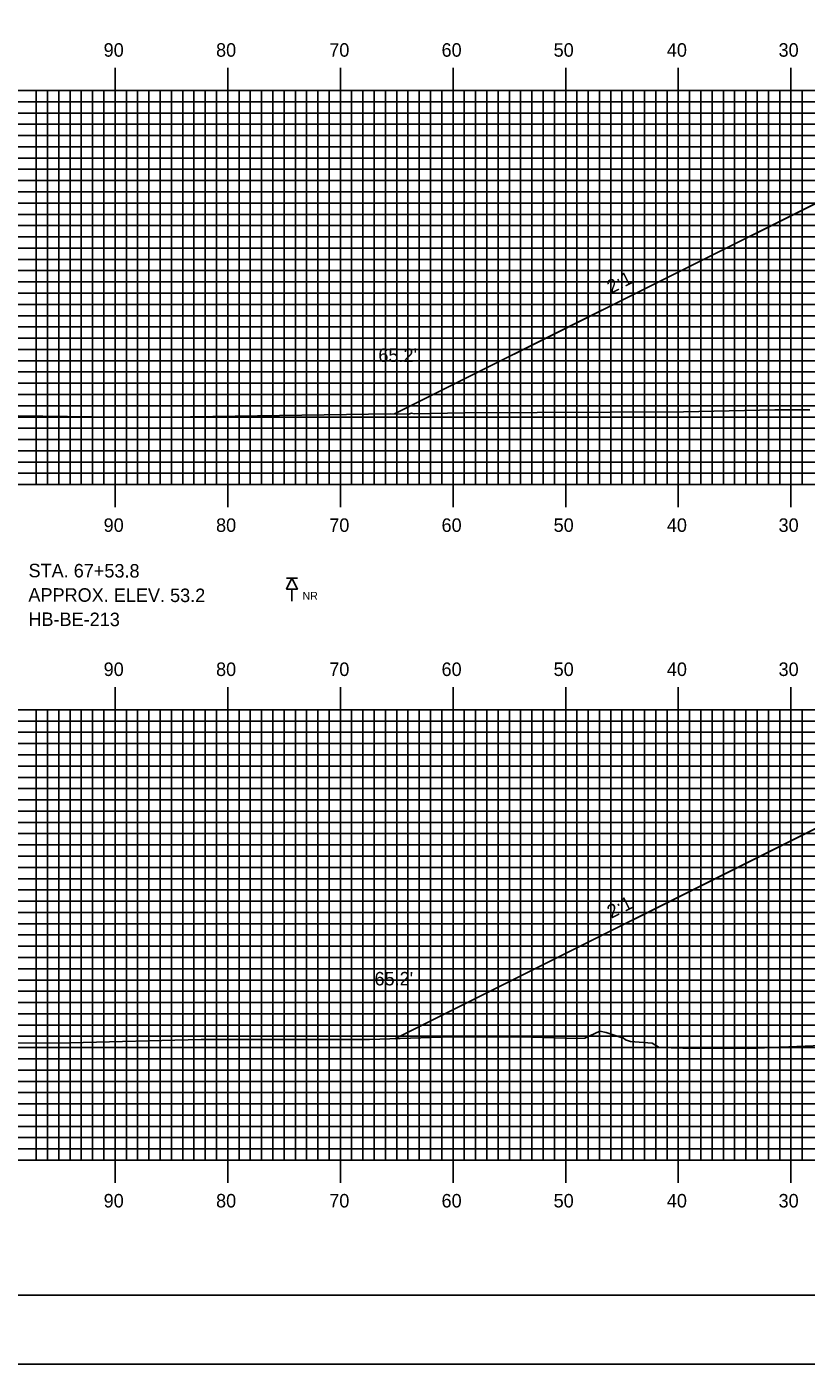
# Model space of a CAD drawing. Extents: x 1759430 to 1759773, y 442591 to 442811.
# Drawn here: x 1759497.8 to 1759567, y 442590.5 to 442709.3 of the extents above; entities that cross this region are included whole.
import ezdxf

# ---------------------------------------------------------------- set-up
doc = ezdxf.new("R2010")
doc.units = 0
for name, color, linetype in [('ANNOTATION', 7, 'Continuous'), ('BORDER', 7, 'Continuous'), ('BORING - NO REFUSAL', 7, 'Continuous'), ('D_Roadway_Centerline', 7, 'Continuous'), ('D_Roadway_SlopeLines', 7, 'Continuous'), ('D_Text_Standard', 7, 'Continuous'), ('H_V ANNOTATION', 7, 'Continuous'), ('MAJOR', 7, 'Continuous'), ('MINOR', 7, 'Continuous'), ('PLOT BOUNDARY', 7, 'Continuous'), ('S_Roadway_Centerline', 7, 'Continuous')]:
    doc.layers.add(name, color=color, linetype=linetype)

msp = doc.modelspace()

# ---------------------------------------------------------------- linework, layer by layer
at = {"layer": 'BORDER'}
msp.add_lwpolyline([(1759446.07, 442596.67), (1759766.07, 442596.67), (1759766.07, 442806.67), (1759446.07, 442806.67)], close=True, dxfattribs=at)
at = {"layer": 'BORING - NO REFUSAL'}
for p, q in [((1759521.85, 442660.35), (1759520.89, 442660.35)), ((1759521.37, 442659.39), (1759521.37, 442658.33))]:
    msp.add_line(p, q, dxfattribs=at)
msp.add_lwpolyline([(1759521.37, 442660.35), (1759521.85, 442659.39), (1759520.89, 442659.39)], close=True, dxfattribs=at)
at = {"layer": 'D_Roadway_Centerline'}
for points in [[(1759530.46, 442674.94), (1759567.38, 442693.4), (1759572.67, 442696.04), (1759575.67, 442696.16), (1759583.67, 442696.48), (1759595.67, 442696.91), (1759607.67, 442697.35), (1759619.67, 442697.78), (1759627.67, 442697.46), (1759630.67, 442697.34), (1759635.42, 442694.96), (1759674.27, 442675.54)], [(1759530.5, 442619.46), (1759567.38, 442637.9), (1759572.67, 442640.54), (1759575.67, 442640.66), (1759583.67, 442640.98), (1759595.67, 442641.41), (1759607.67, 442641.85), (1759619.67, 442642.28), (1759627.67, 442641.96), (1759630.67, 442641.84), (1759635.42, 442639.46), (1759673.76, 442620.3)]]:
    msp.add_lwpolyline(points, dxfattribs=at)
at = {"layer": 'D_Roadway_SlopeLines'}
for points in [[(1759572.67, 442696.04), (1759530.46, 442674.94)], [(1759572.67, 442640.54), (1759530.5, 442619.46)]]:
    msp.add_lwpolyline(points, dxfattribs=at)
at = {"layer": 'MAJOR'}
for p, q in [((1759505.67, 442705.67), (1759505.67, 442703.67)), ((1759515.67, 442705.67), (1759515.67, 442703.67)), ((1759525.67, 442705.67), (1759525.67, 442703.67)), ((1759535.67, 442705.67), (1759535.67, 442703.67)), ((1759545.67, 442705.67), (1759545.67, 442703.67)), ((1759555.67, 442705.67), (1759555.67, 442703.67)), ((1759565.67, 442705.67), (1759565.67, 442703.67)), ((1759455.67, 442703.67), (1759735.67, 442703.67)), ((1759455.67, 442703.67), (1759735.67, 442703.67)), ((1759505.67, 442668.67), (1759505.67, 442703.67)), ((1759515.67, 442668.67), (1759515.67, 442703.67)), ((1759525.67, 442668.67), (1759525.67, 442703.67)), ((1759535.67, 442668.67), (1759535.67, 442703.67)), ((1759545.67, 442668.67), (1759545.67, 442703.67)), ((1759555.67, 442668.67), (1759555.67, 442703.67)), ((1759565.67, 442668.67), (1759565.67, 442703.67)), ((1759455.67, 442698.67), (1759735.67, 442698.67)), ((1759455.67, 442693.67), (1759735.67, 442693.67)), ((1759455.67, 442688.67), (1759735.67, 442688.67)), ((1759455.67, 442683.67), (1759735.67, 442683.67)), ((1759455.67, 442678.67), (1759735.67, 442678.67)), ((1759455.67, 442673.67), (1759735.67, 442673.67)), ((1759455.67, 442668.67), (1759735.67, 442668.67)), ((1759455.67, 442668.67), (1759735.67, 442668.67)), ((1759505.67, 442666.66), (1759505.67, 442668.67)), ((1759515.67, 442666.66), (1759515.67, 442668.67)), ((1759525.67, 442666.66), (1759525.67, 442668.67)), ((1759535.67, 442666.66), (1759535.67, 442668.67)), ((1759545.67, 442666.66), (1759545.67, 442668.67)), ((1759555.67, 442666.66), (1759555.67, 442668.67)), ((1759565.67, 442666.66), (1759565.67, 442668.67)), ((1759505.67, 442650.67), (1759505.67, 442648.67)), ((1759515.67, 442650.67), (1759515.67, 442648.67)), ((1759525.67, 442650.67), (1759525.67, 442648.67)), ((1759535.67, 442650.67), (1759535.67, 442648.67)), ((1759545.67, 442650.67), (1759545.67, 442648.67)), ((1759555.67, 442650.67), (1759555.67, 442648.67)), ((1759565.67, 442650.67), (1759565.67, 442648.67)), ((1759455.67, 442648.67), (1759735.67, 442648.67)), ((1759455.67, 442648.67), (1759735.67, 442648.67)), ((1759505.67, 442608.67), (1759505.67, 442648.67)), ((1759515.67, 442608.67), (1759515.67, 442648.67)), ((1759525.67, 442608.67), (1759525.67, 442648.67)), ((1759535.67, 442608.67), (1759535.67, 442648.67)), ((1759545.67, 442608.67), (1759545.67, 442648.67)), ((1759555.67, 442608.67), (1759555.67, 442648.67)), ((1759565.67, 442608.67), (1759565.67, 442648.67)), ((1759455.67, 442643.67), (1759735.67, 442643.67)), ((1759455.67, 442638.67), (1759735.67, 442638.67)), ((1759455.67, 442633.67), (1759735.67, 442633.67)), ((1759455.67, 442628.67), (1759735.67, 442628.67)), ((1759455.67, 442623.67), (1759735.67, 442623.67)), ((1759455.67, 442618.67), (1759735.67, 442618.67)), ((1759455.67, 442613.67), (1759735.67, 442613.67)), ((1759455.67, 442608.67), (1759735.67, 442608.67)), ((1759455.67, 442608.67), (1759735.67, 442608.67)), ((1759505.67, 442606.66), (1759505.67, 442608.67)), ((1759515.67, 442606.66), (1759515.67, 442608.67)), ((1759525.67, 442606.66), (1759525.67, 442608.67)), ((1759535.67, 442606.66), (1759535.67, 442608.67)), ((1759545.67, 442606.66), (1759545.67, 442608.67)), ((1759555.67, 442606.66), (1759555.67, 442608.67)), ((1759565.67, 442606.66), (1759565.67, 442608.67))]:
    msp.add_line(p, q, dxfattribs=at)
at = {"layer": 'MINOR'}
for p, q in [((1759455.67, 442702.67), (1759735.67, 442702.67)), ((1759498.67, 442668.67), (1759498.67, 442703.67)), ((1759499.67, 442668.67), (1759499.67, 442703.67)), ((1759500.67, 442668.67), (1759500.67, 442703.67)), ((1759501.67, 442668.67), (1759501.67, 442703.67)), ((1759502.67, 442668.67), (1759502.67, 442703.67)), ((1759503.67, 442668.67), (1759503.67, 442703.67)), ((1759504.67, 442668.67), (1759504.67, 442703.67)), ((1759506.67, 442668.67), (1759506.67, 442703.67)), ((1759507.67, 442668.67), (1759507.67, 442703.67)), ((1759508.67, 442668.67), (1759508.67, 442703.67)), ((1759509.67, 442668.67), (1759509.67, 442703.67)), ((1759510.67, 442668.67), (1759510.67, 442703.67)), ((1759511.67, 442668.67), (1759511.67, 442703.67)), ((1759512.67, 442668.67), (1759512.67, 442703.67)), ((1759513.67, 442668.67), (1759513.67, 442703.67)), ((1759514.67, 442668.67), (1759514.67, 442703.67)), ((1759516.67, 442668.67), (1759516.67, 442703.67)), ((1759517.67, 442668.67), (1759517.67, 442703.67)), ((1759518.67, 442668.67), (1759518.67, 442703.67)), ((1759519.67, 442668.67), (1759519.67, 442703.67)), ((1759520.67, 442668.67), (1759520.67, 442703.67)), ((1759521.67, 442668.67), (1759521.67, 442703.67)), ((1759522.67, 442668.67), (1759522.67, 442703.67)), ((1759523.67, 442668.67), (1759523.67, 442703.67)), ((1759524.67, 442668.67), (1759524.67, 442703.67)), ((1759526.67, 442668.67), (1759526.67, 442703.67)), ((1759527.67, 442668.67), (1759527.67, 442703.67)), ((1759528.67, 442668.67), (1759528.67, 442703.67)), ((1759529.67, 442668.67), (1759529.67, 442703.67)), ((1759530.67, 442668.67), (1759530.67, 442703.67)), ((1759531.67, 442668.67), (1759531.67, 442703.67)), ((1759532.67, 442668.67), (1759532.67, 442703.67)), ((1759533.67, 442668.67), (1759533.67, 442703.67)), ((1759534.67, 442668.67), (1759534.67, 442703.67)), ((1759536.67, 442668.67), (1759536.67, 442703.67)), ((1759537.67, 442668.67), (1759537.67, 442703.67)), ((1759538.67, 442668.67), (1759538.67, 442703.67)), ((1759539.67, 442668.67), (1759539.67, 442703.67)), ((1759540.67, 442668.67), (1759540.67, 442703.67)), ((1759541.67, 442668.67), (1759541.67, 442703.67)), ((1759542.67, 442668.67), (1759542.67, 442703.67)), ((1759543.67, 442668.67), (1759543.67, 442703.67)), ((1759544.67, 442668.67), (1759544.67, 442703.67)), ((1759546.67, 442668.67), (1759546.67, 442703.67)), ((1759547.67, 442668.67), (1759547.67, 442703.67)), ((1759548.67, 442668.67), (1759548.67, 442703.67)), ((1759549.67, 442668.67), (1759549.67, 442703.67)), ((1759550.67, 442668.67), (1759550.67, 442703.67)), ((1759551.67, 442668.67), (1759551.67, 442703.67)), ((1759552.67, 442668.67), (1759552.67, 442703.67)), ((1759553.67, 442668.67), (1759553.67, 442703.67)), ((1759554.67, 442668.67), (1759554.67, 442703.67)), ((1759556.67, 442668.67), (1759556.67, 442703.67)), ((1759557.67, 442668.67), (1759557.67, 442703.67)), ((1759558.67, 442668.67), (1759558.67, 442703.67)), ((1759559.67, 442668.67), (1759559.67, 442703.67)), ((1759560.67, 442668.67), (1759560.67, 442703.67)), ((1759561.67, 442668.67), (1759561.67, 442703.67)), ((1759562.67, 442668.67), (1759562.67, 442703.67)), ((1759563.67, 442668.67), (1759563.67, 442703.67)), ((1759564.67, 442668.67), (1759564.67, 442703.67)), ((1759566.67, 442668.67), (1759566.67, 442703.67)), ((1759455.67, 442701.67), (1759735.67, 442701.67)), ((1759455.67, 442700.67), (1759735.67, 442700.67)), ((1759455.67, 442699.67), (1759735.67, 442699.67)), ((1759455.67, 442697.67), (1759735.67, 442697.67)), ((1759455.67, 442696.67), (1759735.67, 442696.67)), ((1759455.67, 442695.67), (1759735.67, 442695.67)), ((1759455.67, 442694.67), (1759735.67, 442694.67)), ((1759455.67, 442692.67), (1759735.67, 442692.67)), ((1759455.67, 442691.67), (1759735.67, 442691.67)), ((1759455.67, 442690.67), (1759735.67, 442690.67)), ((1759455.67, 442689.67), (1759735.67, 442689.67)), ((1759455.67, 442687.67), (1759735.67, 442687.67)), ((1759455.67, 442686.67), (1759735.67, 442686.67)), ((1759455.67, 442685.67), (1759735.67, 442685.67)), ((1759455.67, 442684.67), (1759735.67, 442684.67)), ((1759455.67, 442682.67), (1759735.67, 442682.67)), ((1759455.67, 442681.67), (1759735.67, 442681.67)), ((1759455.67, 442680.67), (1759735.67, 442680.67)), ((1759455.67, 442679.67), (1759735.67, 442679.67)), ((1759455.67, 442677.67), (1759735.67, 442677.67)), ((1759455.67, 442676.67), (1759735.67, 442676.67)), ((1759455.67, 442675.67), (1759735.67, 442675.67)), ((1759455.67, 442674.67), (1759735.67, 442674.67)), ((1759455.67, 442672.67), (1759735.67, 442672.67)), ((1759455.67, 442671.67), (1759735.67, 442671.67)), ((1759455.67, 442670.67), (1759735.67, 442670.67)), ((1759455.67, 442669.67), (1759735.67, 442669.67)), ((1759498.67, 442608.67), (1759498.67, 442648.67)), ((1759499.67, 442608.67), (1759499.67, 442648.67)), ((1759500.67, 442608.67), (1759500.67, 442648.67)), ((1759501.67, 442608.67), (1759501.67, 442648.67)), ((1759502.67, 442608.67), (1759502.67, 442648.67)), ((1759503.67, 442608.67), (1759503.67, 442648.67)), ((1759504.67, 442608.67), (1759504.67, 442648.67)), ((1759506.67, 442608.67), (1759506.67, 442648.67)), ((1759507.67, 442608.67), (1759507.67, 442648.67)), ((1759508.67, 442608.67), (1759508.67, 442648.67)), ((1759509.67, 442608.67), (1759509.67, 442648.67)), ((1759510.67, 442608.67), (1759510.67, 442648.67)), ((1759511.67, 442608.67), (1759511.67, 442648.67)), ((1759512.67, 442608.67), (1759512.67, 442648.67)), ((1759513.67, 442608.67), (1759513.67, 442648.67)), ((1759514.67, 442608.67), (1759514.67, 442648.67)), ((1759516.67, 442608.67), (1759516.67, 442648.67)), ((1759517.67, 442608.67), (1759517.67, 442648.67)), ((1759518.67, 442608.67), (1759518.67, 442648.67)), ((1759519.67, 442608.67), (1759519.67, 442648.67)), ((1759520.67, 442608.67), (1759520.67, 442648.67)), ((1759521.67, 442608.67), (1759521.67, 442648.67)), ((1759522.67, 442608.67), (1759522.67, 442648.67)), ((1759523.67, 442608.67), (1759523.67, 442648.67)), ((1759524.67, 442608.67), (1759524.67, 442648.67)), ((1759526.67, 442608.67), (1759526.67, 442648.67)), ((1759527.67, 442608.67), (1759527.67, 442648.67)), ((1759528.67, 442608.67), (1759528.67, 442648.67)), ((1759529.67, 442608.67), (1759529.67, 442648.67)), ((1759530.67, 442608.67), (1759530.67, 442648.67)), ((1759531.67, 442608.67), (1759531.67, 442648.67)), ((1759532.67, 442608.67), (1759532.67, 442648.67)), ((1759533.67, 442608.67), (1759533.67, 442648.67)), ((1759534.67, 442608.67), (1759534.67, 442648.67)), ((1759536.67, 442608.67), (1759536.67, 442648.67)), ((1759537.67, 442608.67), (1759537.67, 442648.67)), ((1759538.67, 442608.67), (1759538.67, 442648.67)), ((1759539.67, 442608.67), (1759539.67, 442648.67)), ((1759540.67, 442608.67), (1759540.67, 442648.67)), ((1759541.67, 442608.67), (1759541.67, 442648.67)), ((1759542.67, 442608.67), (1759542.67, 442648.67)), ((1759543.67, 442608.67), (1759543.67, 442648.67)), ((1759544.67, 442608.67), (1759544.67, 442648.67)), ((1759546.67, 442608.67), (1759546.67, 442648.67)), ((1759547.67, 442608.67), (1759547.67, 442648.67)), ((1759548.67, 442608.67), (1759548.67, 442648.67)), ((1759549.67, 442608.67), (1759549.67, 442648.67)), ((1759550.67, 442608.67), (1759550.67, 442648.67)), ((1759551.67, 442608.67), (1759551.67, 442648.67)), ((1759552.67, 442608.67), (1759552.67, 442648.67)), ((1759553.67, 442608.67), (1759553.67, 442648.67)), ((1759554.67, 442608.67), (1759554.67, 442648.67)), ((1759556.67, 442608.67), (1759556.67, 442648.67)), ((1759557.67, 442608.67), (1759557.67, 442648.67)), ((1759558.67, 442608.67), (1759558.67, 442648.67)), ((1759559.67, 442608.67), (1759559.67, 442648.67)), ((1759560.67, 442608.67), (1759560.67, 442648.67)), ((1759561.67, 442608.67), (1759561.67, 442648.67)), ((1759562.67, 442608.67), (1759562.67, 442648.67)), ((1759563.67, 442608.67), (1759563.67, 442648.67)), ((1759564.67, 442608.67), (1759564.67, 442648.67)), ((1759566.67, 442608.67), (1759566.67, 442648.67)), ((1759455.67, 442647.67), (1759735.67, 442647.67)), ((1759455.67, 442646.67), (1759735.67, 442646.67)), ((1759455.67, 442645.67), (1759735.67, 442645.67)), ((1759455.67, 442644.67), (1759735.67, 442644.67)), ((1759455.67, 442642.67), (1759735.67, 442642.67)), ((1759455.67, 442641.67), (1759735.67, 442641.67)), ((1759455.67, 442640.67), (1759735.67, 442640.67)), ((1759455.67, 442639.67), (1759735.67, 442639.67)), ((1759455.67, 442637.67), (1759735.67, 442637.67)), ((1759455.67, 442636.67), (1759735.67, 442636.67)), ((1759455.67, 442635.67), (1759735.67, 442635.67)), ((1759455.67, 442634.67), (1759735.67, 442634.67)), ((1759455.67, 442632.67), (1759735.67, 442632.67)), ((1759455.67, 442631.67), (1759735.67, 442631.67)), ((1759455.67, 442630.67), (1759735.67, 442630.67)), ((1759455.67, 442629.67), (1759735.67, 442629.67)), ((1759455.67, 442627.67), (1759735.67, 442627.67)), ((1759455.67, 442626.67), (1759735.67, 442626.67)), ((1759455.67, 442625.67), (1759735.67, 442625.67)), ((1759455.67, 442624.67), (1759735.67, 442624.67)), ((1759455.67, 442622.67), (1759735.67, 442622.67)), ((1759455.67, 442621.67), (1759735.67, 442621.67)), ((1759455.67, 442620.67), (1759735.67, 442620.67)), ((1759455.67, 442619.67), (1759735.67, 442619.67)), ((1759455.67, 442617.67), (1759735.67, 442617.67)), ((1759455.67, 442616.67), (1759735.67, 442616.67)), ((1759455.67, 442615.67), (1759735.67, 442615.67)), ((1759455.67, 442614.67), (1759735.67, 442614.67)), ((1759455.67, 442612.67), (1759735.67, 442612.67)), ((1759455.67, 442611.67), (1759735.67, 442611.67)), ((1759455.67, 442610.67), (1759735.67, 442610.67)), ((1759455.67, 442609.67), (1759735.67, 442609.67))]:
    msp.add_line(p, q, dxfattribs=at)
at = {"layer": 'PLOT BOUNDARY'}
msp.add_lwpolyline([(1759429.89, 442590.55), (1759769.89, 442590.55), (1759769.89, 442810.55), (1759429.89, 442810.55)], close=True, dxfattribs=at)
at = {"layer": 'S_Roadway_Centerline'}
for points in [[(1759455.67, 442674.66), (1759461.59, 442674.85), (1759467.75, 442674.83), (1759480.85, 442674.86), (1759483.88, 442674.88), (1759486.06, 442674.93), (1759505.83, 442674.67), (1759508.01, 442674.65), (1759508.44, 442674.64), (1759530.15, 442674.94), (1759531.73, 442674.91), (1759531.98, 442675.01), (1759532.23, 442674.94), (1759536.65, 442675.05), (1759556.12, 442675.12), (1759564.25, 442675.3), (1759567.34, 442675.32)], [(1759455.67, 442619.06), (1759479.21, 442619.13), (1759483.37, 442619.07), (1759501.67, 442619.08), (1759513.32, 442619.4), (1759528.25, 442619.39), (1759534.62, 442619.59), (1759541.74, 442619.62), (1759546.6, 442619.49), (1759547.37, 442619.52), (1759548.69, 442620.13), (1759549.27, 442620), (1759550.6, 442619.56), (1759550.76, 442619.53), (1759550.97, 442619.36), (1759551.43, 442619.21), (1759553.34, 442619.05), (1759553.96, 442618.69), (1759556.06, 442618.61), (1759561.87, 442618.6), (1759576.31, 442619.17)]]:
    msp.add_lwpolyline(points, dxfattribs=at)

# ---------------------------------------------------------------- texts
at = {"layer": 'ANNOTATION'}
for p in [(1759549.71, 442685.6), (1759549.73, 442630.11)]:
    msp.add_text('2:1', height=1.2, rotation=26.5651, dxfattribs=at).set_placement(p)
at = {"layer": 'BORING - NO REFUSAL'}
for s, p in [('STA. 67+53.8', (1759497.98, 442660.44)), ('APPROX. ELEV. 53.2', (1759497.97, 442658.28)), ('HB-BE-213', (1759497.97, 442656.12))]:
    msp.add_text(s, height=1.2, rotation=359.8142, dxfattribs=at).set_placement(p)
msp.add_text('NR', height=0.7, dxfattribs=at).set_placement((1759522.31, 442658.44))
at = {"layer": 'D_Text_Standard'}
for p in [(1759529.04, 442679.56), (1759528.7, 442624.19)]:
    msp.add_text("65.2'", height=1.2, dxfattribs=at).set_placement(p)
at = {"layer": 'H_V ANNOTATION'}
for s, p in [('90', (1759504.65, 442706.67)), ('80', (1759514.63, 442706.67)), ('70', (1759524.68, 442706.67)), ('60', (1759534.65, 442706.67)), ('50', (1759544.6, 442706.67)), ('40', (1759554.65, 442706.67)), ('30', (1759564.57, 442706.67)), ('90', (1759504.65, 442664.47)), ('80', (1759514.63, 442664.47)), ('70', (1759524.68, 442664.47)), ('60', (1759534.65, 442664.47)), ('50', (1759544.6, 442664.47)), ('40', (1759554.65, 442664.47)), ('30', (1759564.57, 442664.47)), ('90', (1759504.65, 442651.67)), ('80', (1759514.63, 442651.67)), ('70', (1759524.68, 442651.67)), ('60', (1759534.65, 442651.67)), ('50', (1759544.6, 442651.67)), ('40', (1759554.65, 442651.67)), ('30', (1759564.57, 442651.67)), ('90', (1759504.65, 442604.47)), ('80', (1759514.63, 442604.47)), ('70', (1759524.68, 442604.47)), ('60', (1759534.65, 442604.47)), ('50', (1759544.6, 442604.47)), ('40', (1759554.65, 442604.47)), ('30', (1759564.57, 442604.47))]:
    msp.add_text(s, height=1.2, dxfattribs=at).set_placement(p)

doc.saveas('drawing.dxf')
